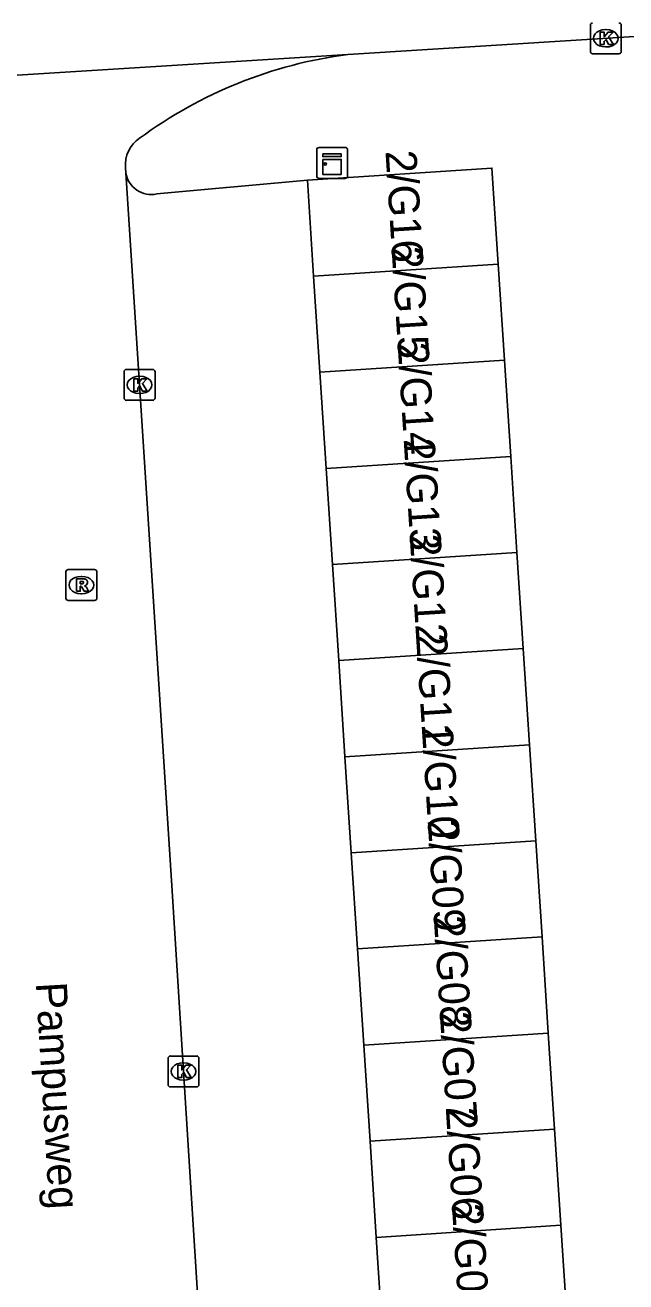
# Model space of a CAD drawing. Extents: x 159689 to 160786, y 387323 to 388339.
# Drawn here: x 160335.15 to 160354.58, y 387792.33 to 387832.98 of the extents above; entities that cross this region are included whole.
import ezdxf

# ---------------------------------------------------------------- set-up
doc = ezdxf.new("R2010")
doc.units = 0
for name, color, linetype in [('IMGEO_Kast', 7, 'Continuous'), ('IMGEO_Kolk', 7, 'Continuous'), ('IMGEO_Openbare_ruimte_label', 7, 'Continuous'), ('IMGEO_Pand', 7, 'Continuous'), ('IMGEO_Pand_nummerreeks', 7, 'Continuous'), ('IMGEO_Rijbaan_lokaal_open', 7, 'Continuous'), ('IMGEO_Rioolput', 7, 'Continuous'), ('IMGEO_Voetpad_open', 7, 'Continuous')]:
    doc.layers.add(name, color=color, linetype=linetype)

msp = doc.modelspace()

# ---------------------------------------------------------------- linework, layer by layer
at = {"layer": 'IMGEO_Kast'}
for p, q in [((160344.581, 387828.1), (160344.581, 387828.941)), ((160344.581, 387828.941), (160344.581, 387828.1)), ((160344.656, 387829.025), (160345.497, 387829.025)), ((160345.497, 387829.025), (160344.656, 387829.025)), ((160345.581, 387828.95), (160345.581, 387828.109)), ((160345.581, 387828.109), (160345.581, 387828.95)), ((160345.506, 387828.025), (160344.665, 387828.025)), ((160344.665, 387828.025), (160345.506, 387828.025))]:
    msp.add_line(p, q, dxfattribs=at)
for points in [[(160344.776, 387828.815), (160345.376, 387828.815), (160345.376, 387828.73), (160344.776, 387828.73), (160344.776, 387828.815)], [(160344.776, 387828.64), (160345.376, 387828.64), (160345.376, 387828.151), (160344.776, 387828.151), (160344.776, 387828.64)]]:
    msp.add_lwpolyline(points, dxfattribs=at)
msp.add_circle((160344.86, 387828.489), 0.0377, dxfattribs=at)
for centre, start, end in [((160344.659, 387828.947), 92.4484, 184.2845), ((160344.659, 387828.947), 92.4484, 184.2845), ((160345.503, 387828.947), 2.4484, 94.2845), ((160345.503, 387828.947), 2.4484, 94.2845), ((160344.659, 387828.103), 182.4484, 274.2845), ((160344.659, 387828.103), 182.4484, 274.2845), ((160345.503, 387828.103), 272.4484, 4.2845), ((160345.503, 387828.103), 272.4484, 4.2845)]:
    msp.add_arc(centre, 0.0779, start, end, dxfattribs=at)
at = {"layer": 'IMGEO_Kolk'}
for p, q in [((160353.435, 387832.129), (160353.435, 387832.981)), ((160354.436, 387832.981), (160354.436, 387832.129)), ((160353.923, 387832.835), (160353.948, 387832.835)), ((160354.362, 387832.055), (160353.51, 387832.055)), ((160353.946, 387832.275), (160353.921, 387832.275)), ((160338.348, 387820.92), (160338.348, 387821.772)), ((160338.423, 387821.846), (160339.275, 387821.846)), ((160338.836, 387821.626), (160338.861, 387821.626)), ((160339.349, 387821.772), (160339.349, 387820.92)), ((160338.859, 387821.066), (160338.834, 387821.066)), ((160339.275, 387820.846), (160338.423, 387820.846)), ((160339.771, 387798.713), (160339.771, 387799.565)), ((160339.846, 387799.639), (160340.698, 387799.639)), ((160340.772, 387799.565), (160340.772, 387798.713)), ((160340.259, 387799.419), (160340.284, 387799.419)), ((160340.282, 387798.859), (160340.257, 387798.859)), ((160340.698, 387798.639), (160339.846, 387798.639))]:
    msp.add_line(p, q, dxfattribs=at)
for points in [[(160353.435, 387832.129), (160353.435, 387832.981)], [(160354.436, 387832.981), (160354.436, 387832.129)], [(160353.756, 387832.755), (160353.879, 387832.755), (160353.879, 387832.604), (160354.009, 387832.755), (160354.173, 387832.755), (160354.027, 387832.604), (160354.18, 387832.355), (160354.028, 387832.355), (160353.943, 387832.519), (160353.879, 387832.452), (160353.879, 387832.355), (160353.756, 387832.355), (160353.756, 387832.755)], [(160354.362, 387832.055), (160353.51, 387832.055)], [(160338.348, 387820.92), (160338.348, 387821.772)], [(160338.423, 387821.846), (160339.275, 387821.846)], [(160338.669, 387821.546), (160338.792, 387821.546), (160338.792, 387821.395), (160338.922, 387821.546), (160339.086, 387821.546), (160338.94, 387821.395), (160339.093, 387821.146), (160338.941, 387821.146), (160338.856, 387821.31), (160338.792, 387821.243), (160338.792, 387821.146), (160338.669, 387821.146), (160338.669, 387821.546)], [(160339.349, 387821.772), (160339.349, 387820.92)], [(160339.275, 387820.846), (160338.423, 387820.846)], [(160339.771, 387798.713), (160339.771, 387799.565)], [(160339.846, 387799.639), (160340.698, 387799.639)], [(160340.772, 387799.565), (160340.772, 387798.713)], [(160340.092, 387799.339), (160340.215, 387799.339), (160340.215, 387799.188), (160340.345, 387799.339), (160340.509, 387799.339), (160340.363, 387799.188), (160340.516, 387798.939), (160340.364, 387798.939), (160340.279, 387799.103), (160340.215, 387799.036), (160340.215, 387798.939), (160340.092, 387798.939), (160340.092, 387799.339)], [(160340.698, 387798.639), (160339.846, 387798.639)]]:
    msp.add_lwpolyline(points, dxfattribs=at)
for centre, start, end in [((160353.512, 387832.979), 91.552, 178.448), ((160353.512, 387832.979), 91.552, 178.448), ((160354.36, 387832.979), 1.552, 88.448), ((160354.36, 387832.979), 1.552, 88.448), ((160353.512, 387832.131), 181.552, 268.448), ((160353.512, 387832.131), 181.552, 268.448), ((160354.36, 387832.131), 271.552, 358.448), ((160354.36, 387832.131), 271.552, 358.448), ((160338.425, 387821.77), 91.552, 178.448), ((160338.425, 387821.77), 91.552, 178.448), ((160339.273, 387821.77), 1.552, 88.448), ((160339.273, 387821.77), 1.552, 88.448), ((160338.425, 387820.922), 181.552, 268.448), ((160338.425, 387820.922), 181.552, 268.448), ((160339.273, 387820.922), 271.552, 358.448), ((160339.273, 387820.922), 271.552, 358.448), ((160339.848, 387799.563), 91.552, 178.448), ((160339.848, 387799.563), 91.552, 178.448), ((160340.696, 387799.563), 1.552, 88.448), ((160340.696, 387799.563), 1.552, 88.448), ((160339.848, 387798.715), 181.552, 268.448), ((160339.848, 387798.715), 181.552, 268.448), ((160340.696, 387798.715), 271.552, 358.448), ((160340.696, 387798.715), 271.552, 358.448)]:
    msp.add_arc(centre, 0.0765, start, end, dxfattribs=at)
for centre, major_axis, ratio, start_param, end_param in [((160353.922, 387832.555), (-0.387, 0.002), 0.722429, 4.712389, 7.853982), ((160353.947, 387832.555), (-0.39, 0.002), 0.717154, 1.570796, 4.712389), ((160338.835, 387821.346), (-0.387, 0.002), 0.722429, 4.712389, 7.853982), ((160338.86, 387821.346), (-0.39, 0.002), 0.717154, 1.570796, 4.712389), ((160340.258, 387799.139), (-0.387, 0.002), 0.722429, 4.712389, 7.853982), ((160340.283, 387799.139), (-0.39, 0.002), 0.717154, 1.570796, 4.712389)]:
    msp.add_ellipse(centre, major_axis=major_axis, ratio=ratio, start_param=start_param, end_param=end_param, dxfattribs=at)
at = {"layer": 'IMGEO_Pand'}
for points in [[(160344.279, 387827.97), (160350.251, 387828.36), (160350.454, 387825.251)], [(160344.279, 387827.97), (160344.482, 387824.862)], [(160344.482, 387824.862), (160350.454, 387825.251)], [(160350.454, 387825.251), (160350.656, 387822.142)], [(160344.482, 387824.862), (160344.684, 387821.753)], [(160350.656, 387822.142), (160344.684, 387821.753)], [(160350.656, 387822.142), (160350.859, 387819.034)], [(160344.684, 387821.753), (160344.887, 387818.644)], [(160344.887, 387818.644), (160350.859, 387819.034)], [(160350.859, 387819.034), (160351.062, 387815.925)], [(160344.887, 387818.644), (160345.09, 387815.535)], [(160345.09, 387815.535), (160351.062, 387815.925)], [(160351.062, 387815.925), (160351.264, 387812.816)], [(160345.292, 387812.427), (160345.09, 387815.535)], [(160351.264, 387812.816), (160345.292, 387812.427)], [(160351.264, 387812.816), (160351.467, 387809.707)], [(160345.292, 387812.427), (160345.495, 387809.318)], [(160345.495, 387809.318), (160351.467, 387809.707)], [(160351.467, 387809.707), (160351.67, 387806.598)], [(160345.495, 387809.318), (160345.698, 387806.209)], [(160345.698, 387806.209), (160351.67, 387806.598)], [(160351.67, 387806.598), (160351.872, 387803.49)], [(160345.9, 387803.1), (160345.698, 387806.209)], [(160351.872, 387803.49), (160345.9, 387803.1)], [(160351.872, 387803.49), (160352.075, 387800.381)], [(160345.9, 387803.1), (160346.103, 387799.991)], [(160346.103, 387799.991), (160352.075, 387800.381)], [(160352.075, 387800.381), (160352.278, 387797.272)], [(160346.103, 387799.991), (160346.306, 387796.883)], [(160346.306, 387796.883), (160352.278, 387797.272)], [(160352.278, 387797.272), (160352.481, 387794.163)], [(160346.306, 387796.883), (160346.509, 387793.774)], [(160352.481, 387794.163), (160346.509, 387793.774)], [(160352.481, 387794.163), (160352.683, 387791.054)], [(160346.509, 387793.774), (160346.711, 387790.665)]]:
    msp.add_lwpolyline(points, dxfattribs=at)
at = {"layer": 'IMGEO_Rijbaan_lokaal_open'}
for points in [[(160355.377, 387832.647), (160345.586, 387832.034)], [(160345.586, 387832.034), (160330.568, 387831.093)], [(160338.406, 387828.202), (160338.395, 387828.368)], [(160341.952, 387772.208), (160341.198, 387784.423), (160339.882, 387805.311), (160338.406, 387828.202)]]:
    msp.add_lwpolyline(points, dxfattribs=at)
for centre, radius, start, end in [((160347.482, 387817.605), 14.553, 97.487, 126.3709), ((160339.432, 387828.459), 1.041, 123.8517, 185.0029)]:
    msp.add_arc(centre, radius, start, end, dxfattribs=at)
at = {"layer": 'IMGEO_Rioolput'}
for p, q in [((160336.542, 387815.372), (160337.394, 387815.372)), ((160336.467, 387814.446), (160336.467, 387815.298)), ((160336.955, 387815.152), (160336.98, 387815.152)), ((160337.468, 387815.298), (160337.468, 387814.446)), ((160336.978, 387814.592), (160336.953, 387814.592)), ((160337.394, 387814.372), (160336.542, 387814.372))]:
    msp.add_line(p, q, dxfattribs=at)
for points in [[(160336.542, 387815.372), (160337.394, 387815.372)], [(160336.467, 387814.446), (160336.467, 387815.298)], [(160337.056, 387815.07), (160336.804, 387815.072), (160336.804, 387814.672)], [(160336.982, 387814.991), (160336.928, 387814.991), (160336.928, 387814.91)], [(160337.468, 387815.298), (160337.468, 387814.446)], [(160336.804, 387814.672), (160336.928, 387814.672), (160336.928, 387814.834), (160336.939, 387814.834)], [(160336.928, 387814.91), (160336.98, 387814.91)], [(160336.986, 387814.805), (160337.057, 387814.672), (160337.197, 387814.672), (160337.132, 387814.798)], [(160337.394, 387814.372), (160336.542, 387814.372)]]:
    msp.add_lwpolyline(points, dxfattribs=at)
for centre, radius, start, end in [((160336.544, 387815.296), 0.0765, 91.552, 178.448), ((160336.544, 387815.296), 0.0765, 91.552, 178.448), ((160337.392, 387815.296), 0.0765, 1.552, 88.448), ((160337.392, 387815.296), 0.0765, 1.552, 88.448), ((160336.988, 387814.895), 0.0964, 77.0061, 93.1865), ((160337.002, 387814.952), 0.0378, 276.6634, 79.6772), ((160337.055, 387814.96), 0.109, 350.3612, 89.416), ((160336.938, 387814.781), 0.0533, 26.0293, 88.6989), ((160336.964, 387815.099), 0.19, 274.7715, 282.9687), ((160337.053, 387814.96), 0.112, 277.5842, 350.9817), ((160337.037, 387814.745), 0.108, 29.5134, 73.7905), ((160336.544, 387814.448), 0.0765, 181.552, 268.448), ((160336.544, 387814.448), 0.0765, 181.552, 268.448), ((160337.392, 387814.448), 0.0765, 271.552, 358.448), ((160337.392, 387814.448), 0.0765, 271.552, 358.448)]:
    msp.add_arc(centre, radius, start, end, dxfattribs=at)
for centre, major_axis, ratio, start_param, end_param in [((160336.954, 387814.872), (-0.387, 0.002), 0.722429, 4.712389, 7.853982), ((160336.979, 387814.872), (-0.39, 0.002), 0.717154, 1.570796, 4.712389)]:
    msp.add_ellipse(centre, major_axis=major_axis, ratio=ratio, start_param=start_param, end_param=end_param, dxfattribs=at)
at = {"layer": 'IMGEO_Voetpad_open'}
msp.add_lwpolyline([(160339.407, 387827.52), (160344.279, 387827.97)], dxfattribs=at)
msp.add_arc((160339.232, 387828.338), 0.837, 189.3694, 282.096, dxfattribs=at)

# ---------------------------------------------------------------- texts
at = {"layer": 'IMGEO_Openbare_ruimte_label'}
msp.add_text('Pampusweg', height=1, rotation=273.3833, dxfattribs=at).set_placement((160335.492, 387802.004))
at = {"layer": 'IMGEO_Pand_nummerreeks'}
for s, p in [('2/G16', (160346.805, 387828.905)), ('2/G15', (160347.001, 387825.8)), ('2/G14', (160347.197, 387822.696)), ('2/G13', (160347.393, 387819.591)), ('2/G12', (160347.588, 387816.493)), ('2/G11', (160347.791, 387813.272)), ('2/G10', (160347.98, 387810.274)), ('2/G09', (160348.17, 387807.267)), ('2/G08', (160348.366, 387804.156)), ('2/G07', (160348.562, 387801.054)), ('2/G06', (160348.757, 387797.95)), ('2/G05', (160348.953, 387794.845))]:
    msp.add_text(s, height=1, rotation=273.6085, dxfattribs=at).set_placement(p)

doc.saveas('drawing.dxf')
